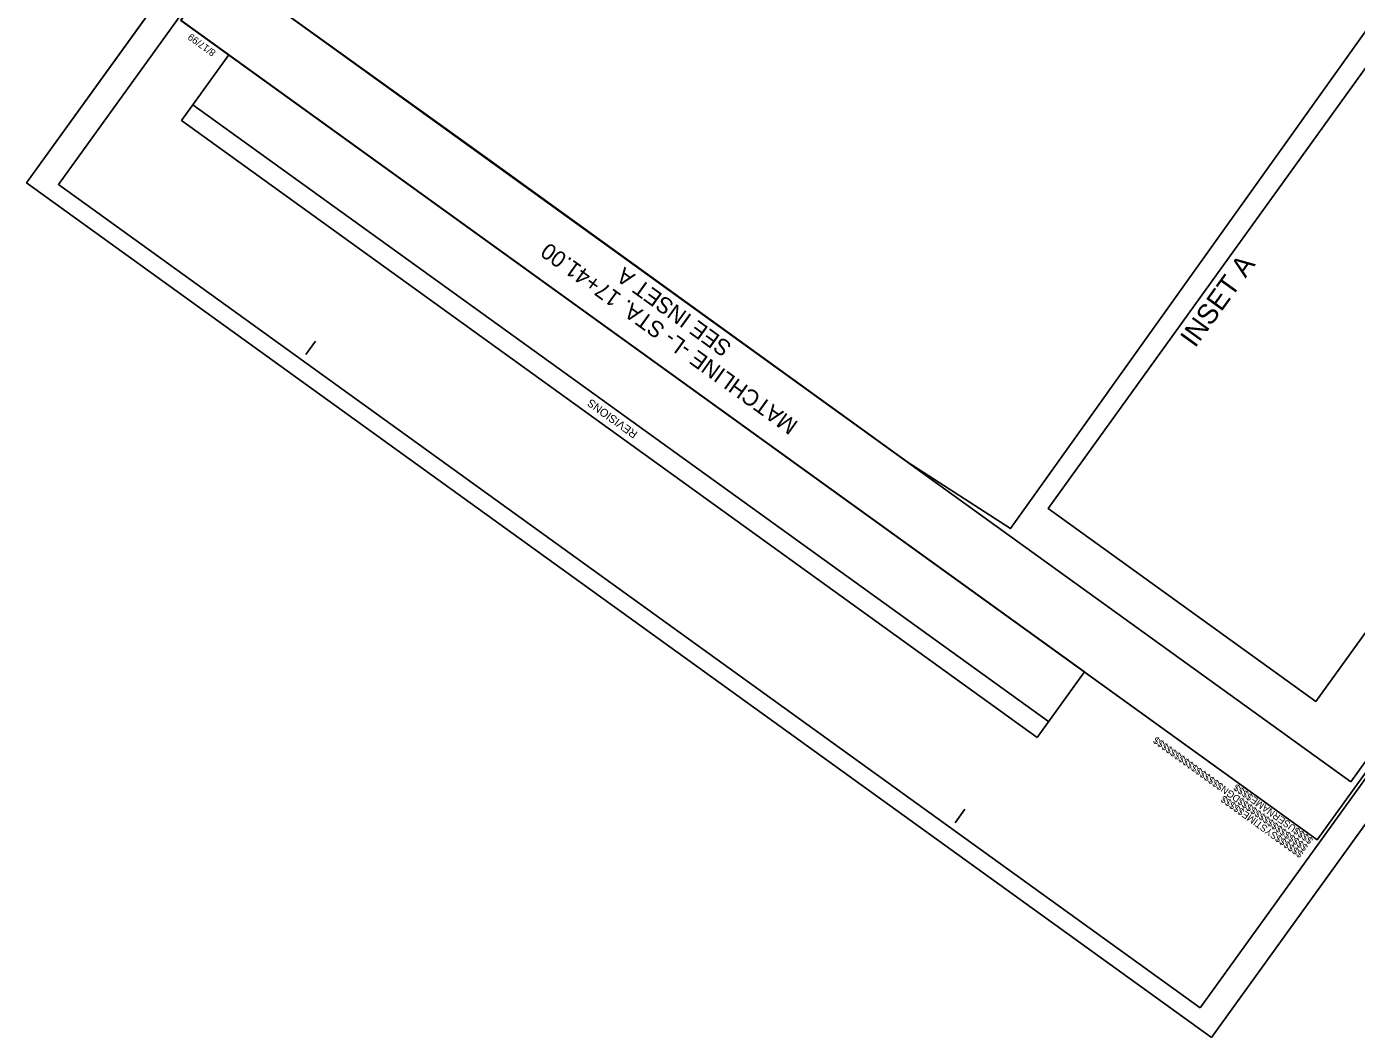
# Model space of a CAD drawing. Extents: x 2186840 to 2191350, y 386817 to 390793.
# Drawn here: x 2189477 to 2190474, y 386817 to 387575 of the extents above; entities that cross this region are included whole.
import ezdxf

# ---------------------------------------------------------------- set-up
doc = ezdxf.new("R2010")
doc.units = 0
for name, color, linetype in [('Matchline', 7, 'Continuous'), ('Matchline Text', 7, 'Continuous'), ('Prop PHM Label Text', 7, 'Continuous'), ('Sheet Block Revision CELL', 7, 'Continuous'), ('Sheet Clip Boundary CELL', 7, 'Continuous'), ('Sheet Cutting Line CELL', 7, 'Continuous'), ('Sheet Layout Plan Border', 7, 'Continuous'), ('Sheet Plan CELL', 7, 'Continuous'), ('Sheet Plan Layout CELL', 7, 'Continuous'), ('Sheet Plot Border Inside CELL', 7, 'Continuous'), ('Sheet Plot Border Outside CELL', 7, 'Continuous')]:
    doc.layers.add(name, color=color, linetype=linetype)

msp = doc.modelspace()

# ---------------------------------------------------------------- linework, layer by layer
at = {"layer": 'Matchline'}
msp.add_line((2190138.13, 387247.68), (2189819.93, 387477.16), dxfattribs=at)
at = {"layer": 'Prop PHM Label Text'}
msp.add_lwpolyline([(2190499.93, 387569.8), (2190242.87, 387213.36), (2190443.58, 387068.62), (2190700.64, 387425.06)], close=True, dxfattribs=at)
at = {"layer": 'Sheet Block Revision CELL'}
msp.add_line((2190243.27, 387053.53), (2189601.99, 387515.99), dxfattribs=at)
msp.add_lwpolyline([(2190234.78, 387041.71), (2189593.49, 387504.19), (2189628.88, 387553.31), (2190270.17, 387090.83)], close=True, dxfattribs=at)
at = {"layer": 'Sheet Clip Boundary CELL'}
msp.add_lwpolyline([(2189820.17, 387477.49), (2190138.13, 387247.68), (2190214.83, 387198.27), (2190505.63, 387605.8), (2190773.91, 387420.42), (2191313.5, 388179.15), (2190637.62, 388666.29), (2190501.89, 388478.1), (2190332.62, 388600.18), (2189623.63, 387618.74)], close=True, dxfattribs=at)
at = {"layer": 'Sheet Cutting Line CELL'}
for p, q in [((2190462.01, 388822.81), (2189477.28, 387457.36)), ((2190365.42, 386816.86), (2191350.15, 388182.31)), ((2189477.28, 387457.36), (2190365.42, 386816.86))]:
    msp.add_line(p, q, dxfattribs=at)
at = {"layer": 'Sheet Layout Plan Border'}
msp.add_lwpolyline([(2190469.75, 387008.54), (2191313.6, 388178.64), (2190637.85, 388665.97), (2190536.83, 388525.9), (2190366.46, 388648.77), (2189623.63, 387618.74)], close=True, dxfattribs=at)
at = {"layer": 'Sheet Plan CELL'}
for p, q in [((2189686.53, 387328.63), (2189693.83, 387338.79)), ((2190173.18, 386977.7), (2190180.5, 386987.83)), ((2190444.54, 386965.06), (2190444.54, 386965.06))]:
    msp.add_line(p, q, dxfattribs=at)
for points in [[(2190470.32, 388795.89), (2189592.9, 387579.24), (2190444.54, 386965.06), (2191321.95, 388181.69)], [(2190444.54, 386965.06), (2189592.91, 387579.2), (2190353.28, 388633.62), (2190475, 388545.85), (2190592.02, 388708.09), (2191321.95, 388181.69)]]:
    msp.add_lwpolyline(points, close=True, dxfattribs=at)
at = {"layer": 'Sheet Plan Layout CELL'}
msp.add_lwpolyline([(2189592.91, 387579.2), (2190444.54, 386965.06), (2191321.94, 388181.68), (2190641.84, 388672.15), (2190501.89, 388478.1), (2190330.36, 388601.81)], close=True, dxfattribs=at)
at = {"layer": 'Sheet Plot Border Inside CELL'}
msp.add_lwpolyline([(2190356.8, 386839.1), (2191331.28, 388190.36), (2190475.6, 388807.46), (2189501.11, 387456.2)], close=True, dxfattribs=at)
at = {"layer": 'Sheet Plot Border Outside CELL'}
msp.add_lwpolyline([(2190365.42, 386816.86), (2191350.15, 388182.31), (2190462.01, 388822.81), (2189477.28, 387457.36)], close=True, dxfattribs=at)

# ---------------------------------------------------------------- texts
at = {"layer": 'Matchline Text'}
for s, p in [('MATCHLINE -L- STA. 17+41.00', (2190056.34, 387277.76)), ('SEE INSET A', (2190006.63, 387336.08))]:
    msp.add_text(s, height=12.15, rotation=144.20184, dxfattribs=at).set_placement(p)
at = {"layer": 'Prop PHM Label Text'}
msp.add_text('INSET A', height=15, rotation=54.20184, dxfattribs=at).set_placement((2190353.1, 387333.12))
at = {"layer": 'Sheet Block Revision CELL'}
msp.add_text('REVISIONS', height=6, rotation=144.20184, dxfattribs=at).set_placement((2189935.81, 387270.27))
at = {"layer": 'Sheet Plan CELL'}
for s, p in [('8/17/99', (2189619.59, 387556.02)), ('$$$$$$$$$$$$$$$$DGN$$$$$$$$$$$$$$$$', (2190438.16, 386960.25)), ('$$$$USERNAME$$$$', (2190441.98, 386965.57)), ('$$$$$$SYSTIME$$$$$', (2190434.62, 386955.3))]:
    msp.add_text(s, height=5.25, rotation=144.20185, dxfattribs=at).set_placement(p)

doc.saveas('drawing.dxf')
